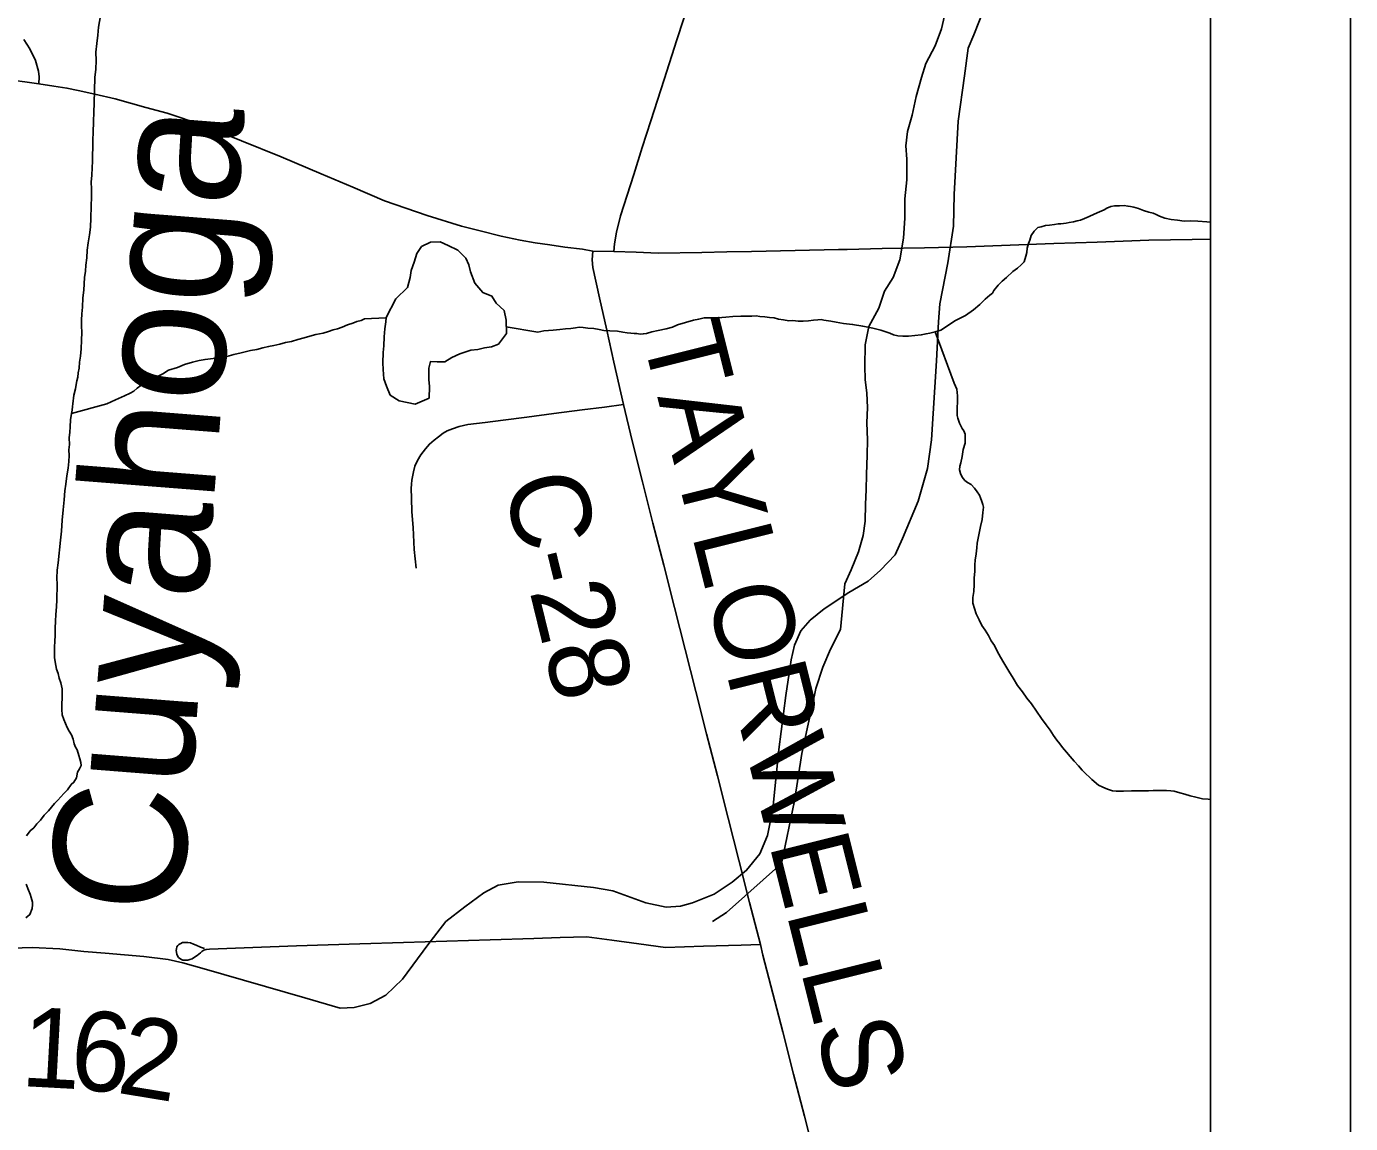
# Model space of a CAD drawing. Extents: x -6.1 to 38, y -7.7 to 22.
# Drawn here: x 8.054 to 9, y 16.217 to 17 of the extents above; entities that cross this region are included whole.
import ezdxf

# ---------------------------------------------------------------- set-up
doc = ezdxf.new("R2010")
doc.units = 0
for name, color, linetype in [('GM_X_Corporation', 7, 'Continuous'), ('GM_X_County_Road', 7, 'Continuous'), ('GM_X_County_Road_Text', 7, 'Continuous'), ('GM_X_Minor_Lake', 7, 'Continuous'), ('GM_X_Minor_River', 7, 'Continuous'), ('GM_X_Minor_River_Text', 7, 'Continuous'), ('GM_X_Township_Road', 7, 'Continuous'), ('GM_X_Township_Road_Text', 7, 'Continuous'), ('GM_X_US_Route', 7, 'Continuous'), ('SH_Data', 7, 'Continuous')]:
    doc.layers.add(name, color=color, linetype=linetype)

msp = doc.modelspace()

# ---------------------------------------------------------------- linework, layer by layer
at = {"layer": 'GM_X_Corporation'}
for points in [[(8.9, 14.85918), (8.9, 19.87135), (8.53815, 19.88018), (8.02661, 19.88922), (8.02125, 19.70471), (8.02079, 19.68982), (8.0189, 19.62846), (7.99279, 18.77986), (7.97287, 17.92154), (7.97183, 17.87641), (7.95308, 17.06692), (7.95307, 17.06643), (7.93594, 16.3267), (7.92512, 16.10977), (7.91657, 15.91251), (7.90988, 15.74002), (7.90533, 15.62285), (7.88899, 15.0865), (7.88923, 14.89059), (8.1023, 14.88375), (8.27757, 14.87811), (8.6137, 14.86789)], [(8.9, 14.68725), (8.9, 19.53649), (8.77571, 19.53237), (8.77312, 19.53228), (6.99327, 19.47331), (6.99349, 19.46054), (7.03821, 16.8882), (7.05054, 16.17866), (7.07262, 15.21743), (7.07601, 15.03919), (7.07603, 15.03845), (7.07902, 14.88093), (7.08348, 14.64684), (7.55487, 14.65733), (8.5875, 14.68029)]]:
    msp.add_lwpolyline(points, close=True, dxfattribs=at)
at = {"layer": 'GM_X_County_Road'}
msp.add_lwpolyline([(8.61764, 16.19167), (8.60991, 16.22176), (8.60217, 16.25185), (8.59444, 16.28194), (8.58737, 16.30943), (8.5803, 16.33691), (8.57841, 16.34443), (8.57074, 16.37453), (8.56306, 16.40464), (8.55539, 16.43474), (8.54772, 16.46485), (8.54004, 16.49495), (8.53237, 16.52506), (8.52469, 16.55516), (8.51702, 16.58527), (8.50935, 16.61538), (8.50168, 16.64548), (8.4942, 16.67482), (8.48673, 16.70415), (8.48073, 16.73007), (8.47385, 16.76037), (8.46863, 16.78333), (8.46342, 16.80628), (8.45882, 16.82807), (8.45821, 16.83345), (8.45871, 16.83965)], dxfattribs=at)
at = {"layer": 'GM_X_Minor_Lake'}
for points in [[(8.34754, 16.76063), (8.3481, 16.7606), (8.35303, 16.76062), (8.35795, 16.76369), (8.36363, 16.76638), (8.37158, 16.76908), (8.37651, 16.76949), (8.38144, 16.77065), (8.38637, 16.77144), (8.39129, 16.77337), (8.39695, 16.78099), (8.39691, 16.79049), (8.39537, 16.79732), (8.38966, 16.8026), (8.3866, 16.80752), (8.38015, 16.81015), (8.37443, 16.81695), (8.37136, 16.82491), (8.37021, 16.82984), (8.36791, 16.83477), (8.3622, 16.84043), (8.35536, 16.84381), (8.34966, 16.84644), (8.34283, 16.84603), (8.3364, 16.84295), (8.333, 16.838), (8.33113, 16.83191), (8.32888, 16.82582), (8.32814, 16.82088), (8.32627, 16.81365), (8.31795, 16.80563), (8.31118, 16.7923)], [(8.31118, 16.7923), (8.31081, 16.78926), (8.31007, 16.78432), (8.30971, 16.77862), (8.30936, 16.77216), (8.309, 16.76722), (8.30865, 16.76001), (8.30905, 16.75507), (8.30945, 16.74861), (8.31137, 16.74331), (8.31405, 16.73687), (8.32051, 16.73272), (8.3319, 16.73051), (8.34175, 16.73474), (8.3421, 16.74309), (8.3417, 16.74803), (8.34166, 16.75601), (8.34278, 16.76095), (8.34754, 16.76063)]]:
    msp.add_lwpolyline(points, dxfattribs=at)
at = {"layer": 'GM_X_Minor_River'}
for points in [[(8.08453, 16.6979), (8.08484, 16.70171), (8.08476, 16.70627), (8.08506, 16.71046), (8.08538, 16.71426), (8.08567, 16.71921), (8.08634, 16.72379), (8.08668, 16.72608), (8.08701, 16.72874), (8.08736, 16.73065), (8.08801, 16.73675), (8.08907, 16.74133), (8.08977, 16.74438), (8.09011, 16.74705), (8.09082, 16.74972), (8.09114, 16.75277), (8.09184, 16.75621), (8.09215, 16.7604), (8.09283, 16.76459), (8.09311, 16.76992), (8.09339, 16.77601), (8.09366, 16.78172), (8.09358, 16.78628), (8.09351, 16.79046), (8.09381, 16.79503), (8.0941, 16.7996), (8.09436, 16.80644), (8.09502, 16.81178), (8.09532, 16.81635), (8.09562, 16.82092), (8.0963, 16.82549), (8.0966, 16.82968), (8.09727, 16.83501), (8.09755, 16.84034), (8.09822, 16.84568), (8.09925, 16.8514), (8.09992, 16.85673), (8.10018, 16.86321), (8.1004, 16.87195), (8.10067, 16.87842), (8.10057, 16.88412), (8.10048, 16.88907), (8.10077, 16.89401), (8.10105, 16.89934), (8.10135, 16.90391), (8.10127, 16.90847), (8.10156, 16.91342), (8.10146, 16.91912), (8.10174, 16.92445), (8.10198, 16.93244), (8.10224, 16.93891), (8.10251, 16.94538), (8.10294, 16.96364), (8.10359, 16.96973), (8.10386, 16.97582), (8.10375, 16.9819), (8.1044, 16.988), (8.10505, 16.99409), (8.10571, 16.99981), (8.10709, 17.00782)], [(8.71002, 17.00789), (8.70779, 16.99841), (8.70329, 16.98627), (8.69652, 16.97374), (8.69352, 16.96387), (8.68978, 16.95021), (8.6868, 16.93694), (8.68343, 16.92518), (8.68233, 16.91494), (8.68311, 16.90546), (8.68316, 16.89068), (8.68169, 16.87703), (8.68173, 16.86339), (8.68064, 16.84898), (8.67804, 16.83343), (8.67317, 16.82091), (8.66714, 16.81103), (8.66302, 16.79889), (8.65588, 16.78598), (8.65327, 16.77271), (8.65294, 16.75755), (8.65335, 16.74807), (8.65451, 16.73822), (8.65492, 16.72798), (8.65458, 16.71699), (8.655, 16.70486), (8.65465, 16.69387), (8.65432, 16.68022), (8.65397, 16.66923), (8.65362, 16.65899), (8.65328, 16.64686), (8.6518, 16.63662), (8.64843, 16.62486), (8.64318, 16.61196), (8.63867, 16.60209), (8.63575, 16.56948), (8.62861, 16.55544), (8.62298, 16.54253), (8.61811, 16.52736), (8.6155, 16.51446), (8.61251, 16.50194), (8.60799, 16.48092)], [(8.78504, 16.85837), (8.78845, 16.85881), (8.7911, 16.85924), (8.793, 16.85927), (8.79679, 16.85972), (8.79906, 16.86014), (8.80209, 16.86058), (8.80473, 16.86138), (8.807, 16.8618), (8.81002, 16.863), (8.81341, 16.86458), (8.8168, 16.86616), (8.82057, 16.86775), (8.82396, 16.86933), (8.82584, 16.87051), (8.82886, 16.8717), (8.83151, 16.87213), (8.83493, 16.87219), (8.83834, 16.87225), (8.84101, 16.87192), (8.84291, 16.87157), (8.8452, 16.87123), (8.84863, 16.87016), (8.85208, 16.8687), (8.8559, 16.86762), (8.85895, 16.86692), (8.86125, 16.86582), (8.86354, 16.86472), (8.86737, 16.86327), (8.87194, 16.86221), (8.87651, 16.86191), (8.88108, 16.86123), (8.88601, 16.86132), (8.89096, 16.86103), (8.89742, 16.86076), (8.9, 16.86041)], [(8.39693, 16.7856), (8.41952, 16.78186), (8.42369, 16.78269), (8.43051, 16.78319), (8.43506, 16.78365), (8.43923, 16.78411), (8.44302, 16.78456), (8.44643, 16.785), (8.44908, 16.78543), (8.45175, 16.78509), (8.45517, 16.78478), (8.45936, 16.78447), (8.46317, 16.78378), (8.4666, 16.78308), (8.47078, 16.78277), (8.47648, 16.7825), (8.48029, 16.7818), (8.48334, 16.78148), (8.486, 16.78115), (8.48828, 16.78081), (8.49018, 16.78084), (8.49247, 16.7805), (8.49475, 16.78054), (8.49702, 16.78096), (8.50079, 16.78217), (8.50534, 16.78301), (8.51101, 16.78426), (8.51555, 16.78548), (8.51932, 16.78707), (8.53065, 16.79031), (8.53443, 16.79114), (8.53822, 16.79197), (8.54277, 16.79205), (8.54809, 16.79215), (8.55378, 16.79263), (8.55871, 16.79309), (8.5644, 16.7932), (8.56782, 16.79326), (8.5701, 16.7933), (8.57238, 16.79334), (8.57541, 16.7934), (8.57808, 16.79306), (8.5815, 16.79274), (8.58493, 16.79243), (8.58835, 16.79211), (8.59141, 16.79102), (8.59483, 16.7907), (8.59864, 16.79001), (8.60168, 16.79006), (8.60548, 16.78975), (8.6089, 16.78981), (8.6127, 16.78988), (8.61649, 16.79033), (8.61952, 16.79076), (8.62179, 16.7908), (8.6237, 16.79046), (8.62865, 16.78979), (8.63246, 16.78909), (8.63779, 16.78805), (8.64426, 16.7874), (8.6515, 16.78601), (8.65875, 16.78462), (8.66447, 16.7832), (8.66867, 16.78176), (8.67096, 16.78104), (8.67364, 16.77995), (8.67669, 16.77924), (8.68012, 16.77892), (8.68429, 16.779), (8.68884, 16.77946), (8.69339, 16.77992), (8.69679, 16.78074), (8.69944, 16.78117), (8.70323, 16.782), (8.70739, 16.78321), (8.7179, 16.79025), (8.72505, 16.79379), (8.73067, 16.7977), (8.73516, 16.80158), (8.73889, 16.80545), (8.74226, 16.80817), (8.74413, 16.80973), (8.74524, 16.81165), (8.7482, 16.8155), (8.75119, 16.81822), (8.75418, 16.82094), (8.75867, 16.8252), (8.76204, 16.82754), (8.76466, 16.82987), (8.7669, 16.83219), (8.76797, 16.83601), (8.76868, 16.83868), (8.769, 16.84173), (8.77008, 16.84517), (8.7708, 16.84747), (8.77188, 16.85091), (8.7741, 16.85399), (8.77671, 16.8567), (8.77898, 16.85712), (8.78201, 16.85794), (8.78504, 16.85837)], [(8.08634, 16.72379), (8.11167, 16.73071), (8.11769, 16.73348), (8.1241, 16.73625), (8.12824, 16.73823), (8.13087, 16.7398), (8.13312, 16.74174), (8.13574, 16.74369), (8.1395, 16.74604), (8.15154, 16.75196), (8.15567, 16.75469), (8.16209, 16.75671), (8.167, 16.7587), (8.17266, 16.76032), (8.17758, 16.76155), (8.18174, 16.76238), (8.18553, 16.76283), (8.18932, 16.76328), (8.19311, 16.76373), (8.19727, 16.76456), (8.20219, 16.76579), (8.20748, 16.76703), (8.21429, 16.76867), (8.21883, 16.76951), (8.22299, 16.77073), (8.22715, 16.77156), (8.23093, 16.77239), (8.2351, 16.77323), (8.23925, 16.77444), (8.24342, 16.77528), (8.24795, 16.7765), (8.25249, 16.77772), (8.25664, 16.77894), (8.2608, 16.78015), (8.2661, 16.78101), (8.26988, 16.78222), (8.27327, 16.78342), (8.2763, 16.78423), (8.2797, 16.78543), (8.28346, 16.78702), (8.28724, 16.78823), (8.29026, 16.78943), (8.29328, 16.79024), (8.29554, 16.79142), (8.31098, 16.79204)], [(8.70323, 16.782), (8.7168, 16.74536), (8.71877, 16.74121), (8.71924, 16.73628), (8.71932, 16.73171), (8.719, 16.72829), (8.71906, 16.72525), (8.71911, 16.7222), (8.71953, 16.72031), (8.72072, 16.71691), (8.72152, 16.71502), (8.72269, 16.71314), (8.72386, 16.71126), (8.72466, 16.709), (8.72478, 16.70253), (8.72334, 16.69794), (8.72267, 16.69299), (8.72161, 16.68841), (8.7209, 16.68611), (8.72056, 16.68345), (8.72137, 16.6808), (8.72256, 16.67816), (8.7245, 16.67591), (8.72642, 16.67443), (8.72911, 16.67295), (8.73143, 16.67033), (8.73338, 16.66771), (8.73494, 16.66545), (8.73573, 16.66357), (8.73654, 16.66092), (8.73734, 16.65865), (8.73775, 16.65676), (8.73744, 16.65295), (8.73677, 16.648), (8.73572, 16.64303), (8.73327, 16.6312), (8.73295, 16.62777), (8.73265, 16.62359), (8.73197, 16.61901), (8.73165, 16.61558), (8.73173, 16.61102), (8.73106, 16.60607), (8.73115, 16.60151), (8.73085, 16.59656), (8.73017, 16.59236), (8.73024, 16.58818), (8.73145, 16.5844), (8.73266, 16.58062), (8.73463, 16.57647), (8.73661, 16.57233), (8.73894, 16.56894), (8.74129, 16.56519), (8.74326, 16.56142), (8.7456, 16.55804), (8.74757, 16.55389), (8.74992, 16.54975), (8.75227, 16.54561), (8.7558, 16.53959), (8.75893, 16.5347), (8.76206, 16.52944), (8.76556, 16.52493), (8.76868, 16.52043), (8.77217, 16.51631), (8.77568, 16.51105), (8.77919, 16.50579), (8.78269, 16.50129), (8.78542, 16.49753), (8.78776, 16.49377), (8.7901, 16.49039), (8.79243, 16.48777), (8.79437, 16.48515), (8.79709, 16.48177), (8.7998, 16.47878), (8.80252, 16.47541), (8.80562, 16.47204), (8.80833, 16.46904), (8.81105, 16.46605), (8.81336, 16.46419), (8.81529, 16.46233), (8.81992, 16.45823), (8.82299, 16.45676), (8.82643, 16.4553), (8.82987, 16.45422), (8.83253, 16.45389), (8.83785, 16.45398), (8.84354, 16.45409), (8.85114, 16.45422), (8.85569, 16.4543), (8.85911, 16.45437), (8.86177, 16.45441), (8.86481, 16.45447), (8.8686, 16.45454), (8.87165, 16.45421), (8.87393, 16.45387), (8.87813, 16.4528), (8.88157, 16.45173), (8.88538, 16.45065), (8.88958, 16.44959)], [(8.05414, 16.42207), (8.05674, 16.42554), (8.05936, 16.42786), (8.06159, 16.43056), (8.0642, 16.43327), (8.06679, 16.43674), (8.06978, 16.43984), (8.072, 16.44254), (8.07424, 16.44524), (8.07647, 16.44756), (8.07871, 16.44988), (8.08095, 16.4522), (8.08356, 16.45491), (8.08615, 16.45876), (8.08802, 16.46032), (8.08986, 16.46339), (8.09055, 16.46759), (8.09203, 16.4699), (8.09312, 16.47219), (8.09308, 16.47448), (8.09228, 16.47712), (8.09147, 16.47939), (8.09026, 16.48355), (8.08909, 16.48543), (8.08829, 16.4877), (8.08747, 16.49111), (8.08628, 16.49413), (8.08471, 16.49676), (8.08314, 16.49939), (8.08195, 16.50241), (8.08076, 16.50505), (8.07956, 16.50845), (8.07949, 16.51226), (8.07943, 16.51606), (8.07972, 16.52063), (8.07967, 16.52367), (8.07961, 16.52709), (8.07877, 16.53126), (8.07757, 16.53465), (8.07675, 16.53806), (8.07556, 16.54108), (8.07513, 16.54374), (8.07471, 16.54639), (8.07427, 16.54943), (8.07422, 16.55247), (8.07414, 16.55703), (8.07445, 16.56084), (8.07475, 16.5654), (8.07466, 16.57034), (8.07495, 16.57529), (8.07524, 16.58024), (8.07552, 16.58557), (8.07581, 16.59052), (8.07575, 16.59432), (8.07606, 16.59813), (8.07599, 16.60193), (8.07592, 16.60611), (8.07619, 16.61182), (8.07686, 16.61715), (8.07847, 16.63315), (8.07911, 16.63963), (8.07973, 16.64762), (8.08036, 16.65486), (8.08099, 16.66209), (8.08164, 16.66857), (8.08231, 16.67315), (8.08296, 16.67924), (8.08401, 16.68458), (8.0843, 16.68953), (8.0846, 16.69372), (8.08453, 16.6979)], [(8.60799, 16.48092), (8.60281, 16.44708), (8.59349, 16.40233), (8.55431, 16.36739), (8.54414, 16.36093)], [(8.88958, 16.44959), (8.89416, 16.44853), (8.89834, 16.44822), (8.9, 16.44802)], [(8.05367, 16.3635), (8.05667, 16.36584), (8.05811, 16.37004), (8.05844, 16.37271), (8.05841, 16.37461), (8.05759, 16.37802), (8.05679, 16.38029), (8.0556, 16.38331), (8.054, 16.38746)]]:
    msp.add_lwpolyline(points, dxfattribs=at)
at = {"layer": 'GM_X_Township_Road'}
for points in [[(8.02182, 16.34101), (8.05827, 16.34241), (8.078, 16.34125), (8.09518, 16.33939), (8.11028, 16.33823), (8.1379, 16.33591), (8.15532, 16.33382), (8.16577, 16.33126), (8.18109, 16.32709), (8.25306, 16.30642), (8.27814, 16.29899), (8.28836, 16.29946), (8.29973, 16.30225), (8.31087, 16.30828), (8.32272, 16.31966), (8.34082, 16.34427), (8.35383, 16.36075), (8.36729, 16.37143), (8.38099, 16.38141), (8.3912, 16.38675), (8.40537, 16.38908), (8.42371, 16.38885), (8.45923, 16.38513), (8.47293, 16.38281), (8.49661, 16.37422), (8.51101, 16.3712), (8.52146, 16.37189), (8.53005, 16.37422), (8.54537, 16.38048), (8.55837, 16.38885), (8.56859, 16.39743), (8.57811, 16.40928), (8.58345, 16.42228), (8.5874, 16.44131), (8.59157, 16.4838), (8.59668, 16.52234), (8.60039, 16.54789), (8.60272, 16.55833), (8.60736, 16.56855), (8.6141, 16.57621), (8.62408, 16.58411), (8.64172, 16.59594), (8.65542, 16.60407), (8.66425, 16.61173), (8.67469, 16.62287), (8.68003, 16.63449), (8.69118, 16.66119), (8.69791, 16.6844), (8.7007, 16.70483), (8.70418, 16.76125), (8.70562, 16.78913), (8.70673, 16.80211), (8.7123, 16.83137), (8.71649, 16.8576), (8.71695, 16.88013), (8.71974, 16.93259), (8.72415, 16.96487), (8.72693, 16.9846), (8.73088, 16.99435), (8.74406, 17.0275)], [(8.47374, 16.83955), (8.47415, 16.84503), (8.47567, 16.85326), (8.47845, 16.86499), (8.48795, 16.89457), (8.49409, 16.91364), (8.50021, 16.93271), (8.50969, 16.9623), (8.51881, 16.99076), (8.52793, 17.01922)], [(8.05236, 16.99097), (8.05662, 16.98428), (8.06049, 16.97594), (8.06282, 16.96833), (8.06333, 16.96416), (8.06302, 16.95929)], [(8.33245, 16.61318), (8.33117, 16.62668), (8.33029, 16.64224), (8.3295, 16.65356), (8.32911, 16.66333), (8.32898, 16.67015), (8.32922, 16.67335), (8.3295, 16.67619), (8.33052, 16.68198), (8.33168, 16.68609), (8.33348, 16.69021), (8.33592, 16.6942), (8.33914, 16.69841), (8.34197, 16.70191), (8.34529, 16.7047), (8.3484, 16.70718), (8.35187, 16.70976), (8.3547, 16.7113), (8.35843, 16.71284), (8.36332, 16.71452), (8.36949, 16.7158), (8.38186, 16.71739), (8.39468, 16.71904), (8.41155, 16.72122), (8.43086, 16.7237), (8.45108, 16.7263), (8.46707, 16.72837), (8.48073, 16.73007)], [(8.18142, 16.34148), (8.17846, 16.3426), (8.17532, 16.34386), (8.17336, 16.3447), (8.17126, 16.34554), (8.16923, 16.34596), (8.16559, 16.34575), (8.16432, 16.34526), (8.16306, 16.34449), (8.16222, 16.34365), (8.16166, 16.34274), (8.16132, 16.34134), (8.16117, 16.34015), (8.16145, 16.33741), (8.16216, 16.33622), (8.16286, 16.33517), (8.16432, 16.33405), (8.16594, 16.33328), (8.16804, 16.33314), (8.16944, 16.33328), (8.17091, 16.33363), (8.17245, 16.33419), (8.17358, 16.33489), (8.17609, 16.33657), (8.1784, 16.3386), (8.17953, 16.33951), (8.18094, 16.34049), (8.18254, 16.34098), (8.18485, 16.3412), (8.2159, 16.3423), (8.24695, 16.3434), (8.26964, 16.3442), (8.29233, 16.34501), (8.32338, 16.34596), (8.35444, 16.3469), (8.38549, 16.34784), (8.41655, 16.34879), (8.43548, 16.34937), (8.45442, 16.34994), (8.47228, 16.34754), (8.49152, 16.34496), (8.51075, 16.34236), (8.53769, 16.34318), (8.56462, 16.344), (8.57841, 16.34443)]]:
    msp.add_lwpolyline(points, dxfattribs=at)
at = {"layer": 'GM_X_US_Route'}
for points in [[(7.93016, 16.96472), (7.9389, 16.9649), (7.95841, 16.96529), (7.97791, 16.96569), (7.99411, 16.96523), (8.01031, 16.96477), (8.02575, 16.96345), (8.03834, 16.96254), (8.05307, 16.96061), (8.06302, 16.95929)], [(8.06302, 16.95929), (8.0736, 16.95768), (8.08303, 16.95614), (8.09105, 16.95452), (8.10304, 16.95188), (8.11746, 16.94863), (8.1395, 16.94233), (8.15463, 16.93816), (8.17952, 16.92984), (8.20775, 16.91852), (8.23599, 16.90719), (8.26456, 16.895), (8.28729, 16.8853), (8.31002, 16.8756), (8.32516, 16.87037), (8.34029, 16.86514), (8.36497, 16.85752), (8.37827, 16.85417), (8.39331, 16.85051), (8.40691, 16.84767), (8.41748, 16.84574), (8.42804, 16.84412), (8.4387, 16.84259), (8.4513, 16.84118), (8.45871, 16.83965), (8.47374, 16.83955), (8.48964, 16.83889), (8.50553, 16.83823), (8.53659, 16.83882), (8.55438, 16.83916), (8.57218, 16.83949), (8.60324, 16.84016), (8.6343, 16.84082), (8.64032, 16.84095)], [(8.64032, 16.84095), (8.66537, 16.84149), (8.69565, 16.84213), (8.72593, 16.84278), (8.75698, 16.84392), (8.78803, 16.84506), (8.81908, 16.84621), (8.83747, 16.84689), (8.85585, 16.84756), (8.88692, 16.848), (8.9, 16.84818)]]:
    msp.add_lwpolyline(points, dxfattribs=at)
at = {"layer": 'SH_Data'}
for p, q in [((9, 21), (9, 14)), ((8.9, 20.9), (8.9, 14.1))]:
    msp.add_line(p, q, dxfattribs=at)

# ---------------------------------------------------------------- texts
at = {"layer": 'GM_X_County_Road_Text'}
for s, height, rotation, p in [('TAYLORWELLS', 0.0568182, 284.03796, (8.49346, 16.78079)), ('C-28', 0.056818, 283.77894, (8.39432, 16.675))]:
    msp.add_text(s, height=height, rotation=rotation, dxfattribs=at).set_placement(p)
at = {"layer": 'GM_X_Minor_River_Text'}
msp.add_text('Cuyahoga', height=0.094763, rotation=85.49315, dxfattribs=at).set_placement((8.16461, 16.36441))
at = {"layer": 'GM_X_Township_Road_Text'}
for s, rotation, p in [('1', 356.88656, (8.04955, 16.24338)), ('6', 355.12313, (8.08404, 16.24152)), ('2', 350.6643, (8.11775, 16.23868))]:
    msp.add_text(s, height=0.05682, rotation=rotation, dxfattribs=at).set_placement(p)

doc.saveas('drawing.dxf')
